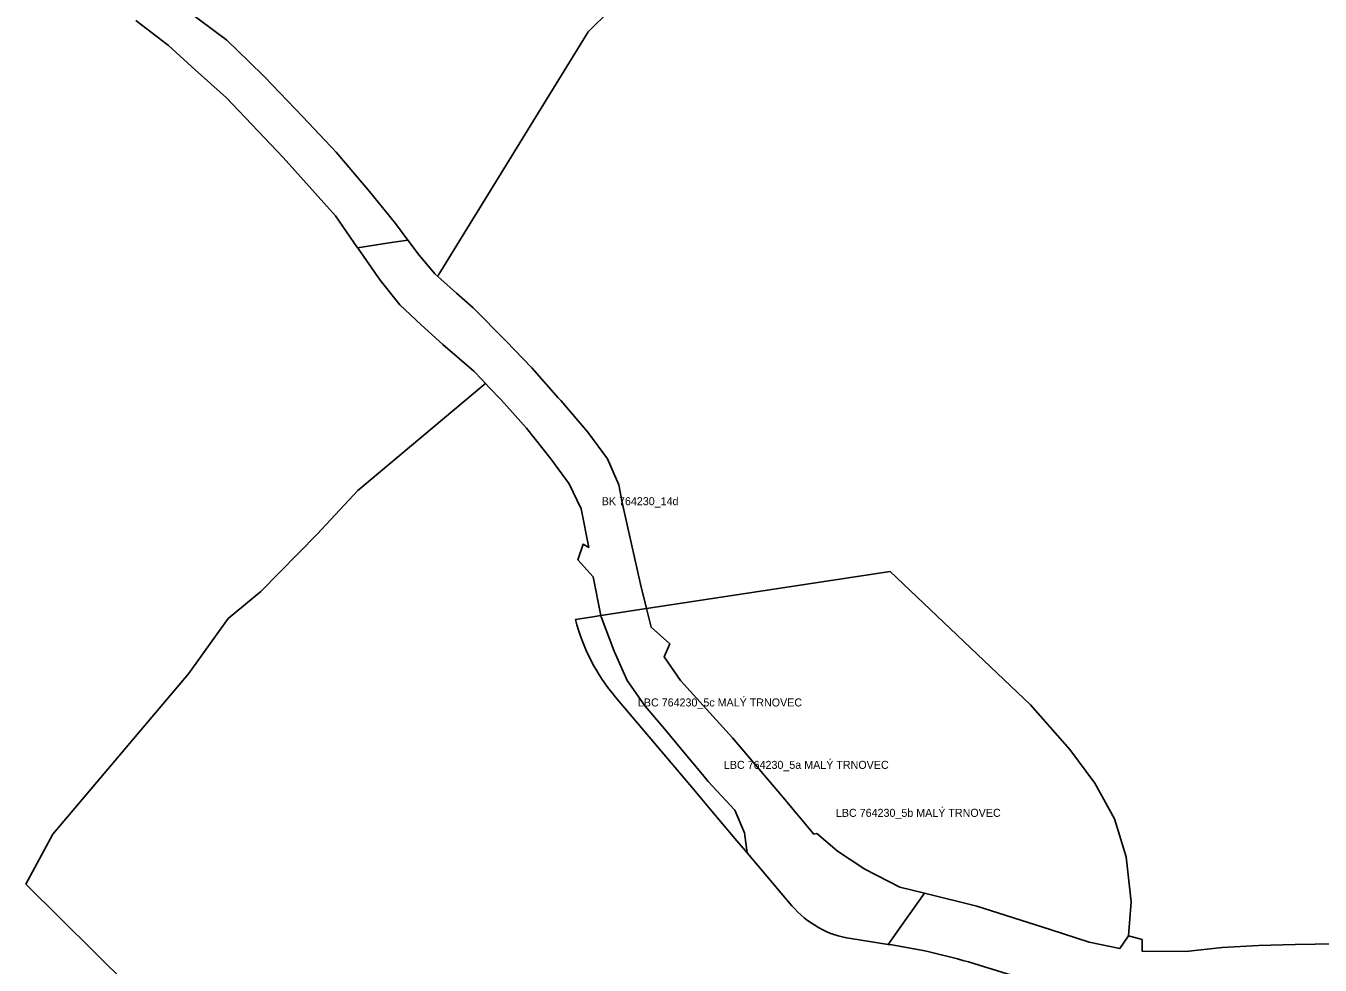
# Model space of a CAD drawing. Extents: x -521616 to -516782, y -1190061 to -1184927.
# Drawn here: x -518534 to -517887, y -1187893 to -1187423 of the extents above; entities that cross this region are included whole.
import ezdxf

# ---------------------------------------------------------------- set-up
doc = ezdxf.new("R2010")
doc.units = 0
for name, color, linetype in [('i_prvek_l_n', 7, 'Continuous'), ('i_prvek_l_s', 7, 'Continuous'), ('LBC_n', 7, 'Continuous'), ('LBC_s', 7, 'Continuous'), ('LBK_n', 7, 'Continuous'), ('LBK_s', 7, 'Continuous')]:
    doc.layers.add(name, color=color, linetype=linetype)

msp = doc.modelspace()

# ---------------------------------------------------------------- linework, layer by layer
at = {"layer": 'i_prvek_l_n'}
for points in [[(-518327.82, -1187548.31), (-518252.88, -1187426.47), (-518241.97, -1187415.84), (-518234.99, -1187412.88), (-518191.26, -1187411.98)], [(-518533.9, -1187852.4), (-518520.38, -1187827.33), (-518452.63, -1187747.23), (-518432.72, -1187719.61), (-518416.45, -1187706.22), (-518388.33, -1187677.45), (-518367.91, -1187655.64), (-518303.97, -1187602.03)]]:
    msp.add_lwpolyline(points, dxfattribs=at)
at = {"layer": 'i_prvek_l_s'}
msp.add_lwpolyline([(-518122.21, -1188421.13), (-518215.84, -1188335.41), (-518261.14, -1188281.69), (-518352.92, -1188101.67), (-518369.92, -1188054.86), (-518403.1, -1187982.61), (-518465.07, -1187920.47), (-518533.9, -1187852.4)], dxfattribs=at)
at = {"layer": 'LBC_n'}
msp.add_lwpolyline([(-518223.7, -1187714.67), (-518101.98, -1187696.13), (-518031.76, -1187762.77), (-518012.17, -1187785.14), (-517999.59, -1187801.95), (-517989.79, -1187819.76), (-517984.01, -1187838.68), (-517981.49, -1187861.2), (-517982.87, -1187878.14), (-517987.04, -1187884.47), (-518002.39, -1187881.3), (-518021.91, -1187875.05), (-518058.64, -1187863.4), (-518084.71, -1187856.91), (-518097.07, -1187853.83), (-518114.58, -1187844.96), (-518128.17, -1187835.85), (-518129.56, -1187834.68), (-518138.5, -1187827.13), (-518140.13, -1187827.37), (-518156.25, -1187808.15), (-518180.64, -1187779.29), (-518206.72, -1187750.59), (-518214.82, -1187738.71), (-518212.12, -1187732.3), (-518221.38, -1187724.04)], close=True, dxfattribs=at)
msp.add_lwpolyline([(-518259.27, -1187720.09), (-518251.5, -1187718.91), (-518246.56, -1187718.16), (-518246.42, -1187718.84), (-518239.93, -1187735.97), (-518233.45, -1187750.63), (-518224.35, -1187763.44), (-518214.78, -1187774.7), (-518205.21, -1187786.28), (-518195.75, -1187797.63), (-518192.87, -1187801.09), (-518179.59, -1187815.44), (-518174.66, -1187826.75), (-518173.4, -1187836.69), (-518179.48, -1187829.5), (-518191.88, -1187814.84), (-518200.28, -1187804.91), (-518239.19, -1187758.93)], dxfattribs=at)
msp.add_arc((-518164.37, -1187695.63), 98, 194.45626, 220.23399, dxfattribs=at)
at = {"layer": 'LBC_s'}
for points in [[(-518179.59, -1187815.44), (-518192.87, -1187801.09), (-518195.75, -1187797.63), (-518205.21, -1187786.28), (-518214.78, -1187774.7), (-518224.35, -1187763.44), (-518233.45, -1187750.63), (-518239.93, -1187735.97), (-518246.42, -1187718.84), (-518246.56, -1187718.16), (-518223.7, -1187714.67), (-518221.38, -1187724.04), (-518212.12, -1187732.3), (-518214.82, -1187738.71), (-518206.72, -1187750.59), (-518180.64, -1187779.29), (-518156.25, -1187808.15), (-518140.13, -1187827.37), (-518138.5, -1187827.13), (-518129.56, -1187834.68), (-518128.17, -1187835.85), (-518114.58, -1187844.96), (-518097.07, -1187853.83), (-518084.71, -1187856.91), (-518097.36, -1187874.73)], [(-518150.99, -1187863.17), (-518173.4, -1187836.69), (-518174.66, -1187826.75), (-518179.59, -1187815.44)], [(-518097.36, -1187874.73), (-518102.88, -1187882.5), (-518121.64, -1187879.61)]]:
    msp.add_lwpolyline(points, dxfattribs=at)
msp.add_arc((-518114.34, -1187832.17), 48, 220.23228, 261.25455, dxfattribs=at)
at = {"layer": 'LBK_n'}
msp.add_lwpolyline([(-518352.34, -1187531.97), (-518342.96, -1187530.54), (-518337.35, -1187538.01), (-518330.21, -1187546.55), (-518329.48, -1187547.42), (-518326.5, -1187550.08), (-518318.68, -1187557.07), (-518310.35, -1187564.32), (-518294.06, -1187580.83), (-518281.02, -1187594.41), (-518267.78, -1187609.35), (-518266.52, -1187610.77), (-518253.09, -1187626.59), (-518243.14, -1187639.86), (-518237.5, -1187652.9), (-518235.88, -1187661.62), (-518231.25, -1187682.45), (-518226.7, -1187702.52), (-518223.7, -1187714.67), (-518246.56, -1187718.16), (-518250.43, -1187698.77), (-518257.99, -1187690.29), (-518255.37, -1187682.57), (-518252.59, -1187684.11), (-518256.29, -1187664.82), (-518262.31, -1187652.32), (-518271.57, -1187639.82), (-518283.61, -1187624.54), (-518296.42, -1187610.35), (-518302.43, -1187604), (-518304.15, -1187602.18), (-518305.87, -1187600.36), (-518310, -1187595.99), (-518325.58, -1187582.72), (-518336.39, -1187572.85), (-518347.04, -1187562.81), (-518356.76, -1187550.62), (-518367.87, -1187534.73), (-518368.12, -1187534.37)], close=True, dxfattribs=at)
at = {"layer": 'LBK_s'}
for points in [[(-518467.26, -1187405.28), (-518433.48, -1187430.64), (-518422.42, -1187441.37), (-518414.69, -1187448.87), (-518395.52, -1187469.02), (-518378.78, -1187486.62), (-518362.1, -1187506.29), (-518349.16, -1187522.27), (-518342.96, -1187530.54)], [(-518368.12, -1187534.37), (-518379.14, -1187518.37), (-518405.37, -1187489.2), (-518433.61, -1187459.42), (-518449.21, -1187445.4), (-518462.63, -1187433.34), (-518478.98, -1187420.84)], [(-518342.96, -1187530.54), (-518352.34, -1187531.97), (-518368.12, -1187534.37)], [(-518102.88, -1187882.5), (-518097.36, -1187874.73), (-518084.71, -1187856.91), (-518058.64, -1187863.4), (-518021.91, -1187875.05), (-518002.39, -1187881.3), (-517987.04, -1187884.47), (-517982.87, -1187878.14), (-517976, -1187880.07), (-517976, -1187885.85), (-517954.2, -1187886.05), (-517935.99, -1187884.04), (-517917.78, -1187882.96), (-517899.42, -1187882.5), (-517879.51, -1187882.19)], [(-518101.08, -1187882.78), (-518102.88, -1187882.5)], [(-518034.74, -1187899.9), (-518057.46, -1187892.84)]]:
    msp.add_lwpolyline(points, dxfattribs=at)
msp.add_arc((-518147, -1188181.26), 302, 72.75379, 81.25327, dxfattribs=at)

# ---------------------------------------------------------------- texts
at = {"layer": 'LBC_n'}
for s, p in [('LBC 764230_5c MALÝ TRNOVEC', (-518228, -1187763.59)), ('LBC 764230_5b MALÝ TRNOVEC', (-518129.02, -1187818.75))]:
    msp.add_text(s, height=4, dxfattribs=at).set_placement(p)
at = {"layer": 'LBC_s'}
msp.add_text('LBC 764230_5a MALÝ TRNOVEC', height=4, dxfattribs=at).set_placement((-518185.02, -1187794.78))
at = {"layer": 'LBK_n'}
msp.add_text('BK 764230_14d', height=4, dxfattribs=at).set_placement((-518246.07, -1187663.02))

doc.saveas('drawing.dxf')
